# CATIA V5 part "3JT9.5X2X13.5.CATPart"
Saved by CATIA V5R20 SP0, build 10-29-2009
Part number: 3JT9.5X2X13.5
Revision: ANY
Definition: UNKNOWN
Nomenclature: 3JT9.5X2X13.5
Source: Unknown
Bounding box of the stored display mesh (mm): x -6.581 to 6.581, y -1 to 1, z -6.75 to 6.75
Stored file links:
  C:\Users\Utente\Desktop\IO LAVORO\3D X SITO CF\CUMSA\3D files PW\pw081230\pw081230_ejection\3JT9.5X2X13.5.CATPart
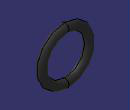
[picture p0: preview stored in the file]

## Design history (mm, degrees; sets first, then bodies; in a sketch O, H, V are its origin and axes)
Body1 "Revolución1" (main body)
  Solid1: solid without history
